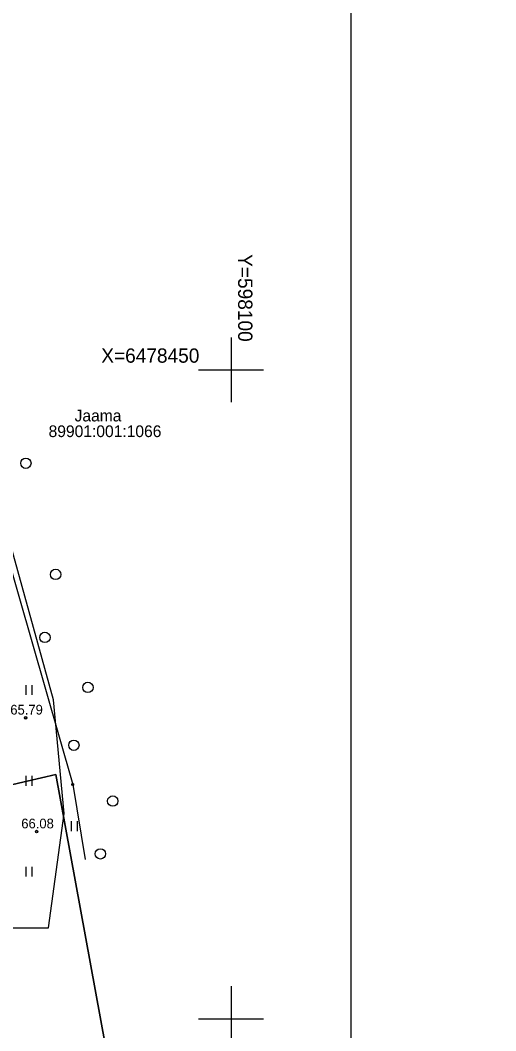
# Model space of a CAD drawing. Extents: x 598011 to 598230, y 6478330 to 6478537.
# Drawn here: x 598083.7 to 598120.4, y 6478399.1 to 6478476.9 of the extents above; entities that cross this region are included whole.
import ezdxf

# ---------------------------------------------------------------- set-up
doc = ezdxf.new("R2010")
doc.units = 0
for name, color, linetype in [('HALJASTUS', 7, 'Continuous'), ('KORGUS-EH2000', 7, 'Continuous'), ('MOOTMPUNKT', 7, 'Continuous'), ('MOOTPIIR', 7, 'Continuous'), ('PIIR', 7, 'Continuous'), ('VORK', 7, 'Continuous'), ('VORMISTUS', 7, 'Continuous')]:
    doc.layers.add(name, color=color, linetype=linetype)

msp = doc.modelspace()

# ---------------------------------------------------------------- linework, layer by layer
at = {"layer": 'HALJASTUS'}
for p, q in [((598084.181, 6478425.714), (598084.181, 6478424.953)), ((598084.636, 6478425.714), (598084.636, 6478424.953)), ((598084.181, 6478418.714), (598084.181, 6478417.953)), ((598084.636, 6478418.714), (598084.636, 6478417.953)), ((598087.681, 6478415.214), (598087.681, 6478414.453)), ((598088.136, 6478415.214), (598088.136, 6478414.453)), ((598084.181, 6478411.714), (598084.181, 6478410.953)), ((598084.636, 6478411.714), (598084.636, 6478410.953))]:
    msp.add_line(p, q, dxfattribs=at)
msp.add_lwpolyline([(598074.027, 6478475.285), (598073.77, 6478466.095), (598078.481, 6478457.792), (598076.946, 6478452.332), (598080.553, 6478445.829), (598081.491, 6478439.919), (598087.787, 6478418.044), (598088.752, 6478412.268)], dxfattribs=at)
for centre in [(598084.175, 6478442.8), (598086.474, 6478434.238), (598085.644, 6478429.382), (598088.963, 6478425.532), (598087.878, 6478421.075), (598090.879, 6478416.778), (598089.921, 6478412.705)]:
    msp.add_circle(centre, 0.4, dxfattribs=at)
at = {"layer": 'KORGUS-EH2000'}
for centre in [(598084.16, 6478423.189), (598085.006, 6478414.42)]:
    msp.add_circle(centre, 0.1, dxfattribs=at)
at = {"layer": 'MOOTMPUNKT'}
for centre in [(598084.16, 6478423.189), (598087.787, 6478418.044), (598085.006, 6478414.42)]:
    msp.add_circle(centre, 0.075, dxfattribs=at)
at = {"layer": 'MOOTPIIR'}
msp.add_lwpolyline([(598075.982, 6478475.56), (598057.177, 6478472.92), (598048.24, 6478469.789), (598045.814, 6478449.279), (598044.645, 6478438.772), (598046.991, 6478414.508), (598054.253, 6478402.767), (598060.844, 6478399.077), (598071.972, 6478405.5), (598083.023, 6478407.009), (598085.912, 6478407.009), (598087.125, 6478415.828), (598086.295, 6478424.582), (598081.666, 6478441.29), (598079.041, 6478458.618)], close=True, dxfattribs=at)
at = {"layer": 'PIIR'}
for points in [[(598093.38, 6478381.19), (598086.49, 6478418.82), (598083.16, 6478418.05), (598080.86, 6478427.08), (598077.2, 6478441.43), (598071.55, 6478454.2), (598069.29, 6478462.69), (598069.71, 6478474.66), (598073.69, 6478488.47), (598079.22, 6478501.09), (598086.45, 6478519.6), (598092.94, 6478530.49), (598127.2, 6478509.56), (598154.27, 6478492.13), (598192.62, 6478466.21), (598223.81, 6478441.55), (598229.65, 6478435.94), (598191.25, 6478412.44), (598173.37, 6478396.18), (598161.58, 6478385.58), (598151.68, 6478381.11), (598144.54, 6478375.38)], [(598130.96, 6478330.09), (598110.14, 6478369.56), (598053.52, 6478386.1), (598050.5, 6478410.56), (598069.31, 6478414.97), (598077.61, 6478417.15), (598083.16, 6478418.05), (598086.49, 6478418.82), (598093.38, 6478381.19), (598154.28, 6478374.27), (598158.87, 6478339.87), (598159.68, 6478333.85)]]:
    msp.add_lwpolyline(points, close=True, dxfattribs=at)
at = {"layer": 'VORK'}
for p, q in [((598100, 6478452.5), (598100, 6478447.5)), ((598097.5, 6478450), (598102.5, 6478450)), ((598100, 6478402.5), (598100, 6478397.5)), ((598097.5, 6478400), (598102.5, 6478400))]:
    msp.add_line(p, q, dxfattribs=at)
at = {"layer": 'VORMISTUS'}
msp.add_lwpolyline([(598109.249, 6478361.639), (598016.749, 6478361.639), (598016.749, 6478504.139), (598109.249, 6478504.139), (598109.249, 6478361.639)], dxfattribs=at)

# ---------------------------------------------------------------- texts
at = {"layer": 'KORGUS-EH2000'}
for s, p in [('65.79', (598082.976, 6478423.439)), ('66.08', (598083.822, 6478414.67))]:
    msp.add_text(s, height=0.75, dxfattribs=at).set_placement(p)
at = {"layer": 'PIIR'}
for s, p in [('Jaama', (598087.934, 6478446.025)), ('89901:001:1066', (598085.929, 6478444.819))]:
    msp.add_text(s, height=0.9, dxfattribs=at).set_placement(p)
at = {"layer": 'VORK'}
msp.add_text('Y=598100', height=1.1, rotation=270, dxfattribs=at).set_placement((598100.55, 6478458.917))
msp.add_text('X=6478450', height=1.1, dxfattribs=at).set_placement((598089.992, 6478450.55))

doc.saveas('drawing.dxf')
